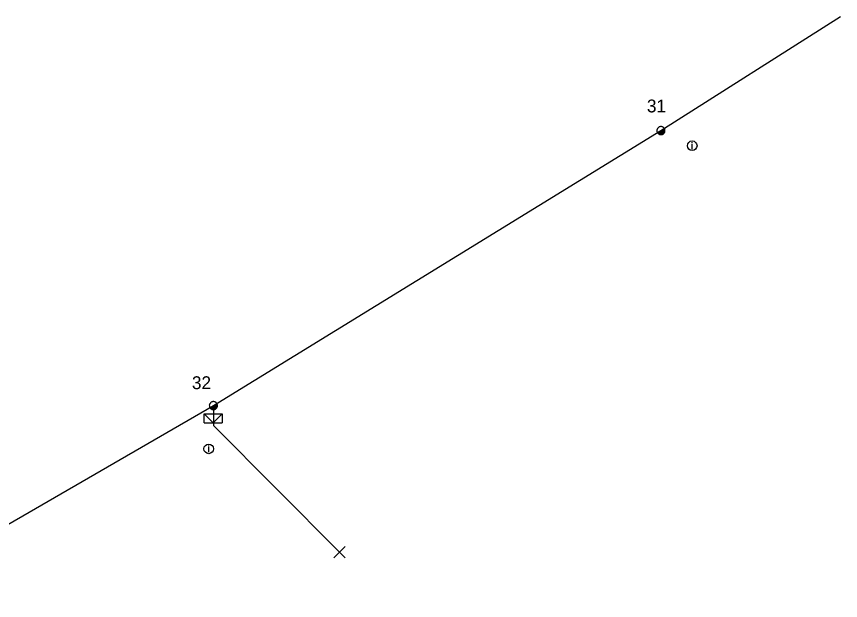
# Model space of a CAD drawing. Extents: x -536148 to -535465, y -1201639 to -1201298.
# Drawn here: x -535529.3 to -535465.3, y -1201539 to -1201493.6 of the extents above; entities that cross this region are included whole.
import ezdxf

# ---------------------------------------------------------------- set-up
doc = ezdxf.new("R2010")
doc.units = 0
for name, color, linetype in [('CHRAN_NN', 7, 'Continuous'), ('CIZÍ_PODZEM', 7, 'Continuous'), ('CIZÍ_PODZEM_POPIS', 7, 'Continuous'), ('DOPLŇ_POPISY', 7, 'Continuous'), ('ELE_EON', 7, 'Continuous'), ('ELE_EON_POPIS', 7, 'Continuous'), ('KN_VKP_HRAN_NEZNATELNÁ', 7, 'Continuous'), ('KN_VKP_HRAN_SPORNÁ', 7, 'Continuous'), ('PK_HRAN_POHYBLIVÁ', 7, 'Continuous'), ('PLG_EXPORT_GPE', 7, 'Continuous')]:
    doc.layers.add(name, color=color, linetype=linetype)

# ---------------------------------------------------------------- blocks, each defined once
blk = doc.blocks.new('NN440')
at = {"layer": 'ELE_EON_POPIS'}
for points in [[(0.63, 0), (0.63, 0.06), (0.62, 0.13), (0.6, 0.19), (0.58, 0.25), (0.55, 0.31), (0.51, 0.37), (0.47, 0.42), (0.42, 0.46), (0.37, 0.51), (0.32, 0.54), (0.26, 0.57), (0.2, 0.59), (0.13, 0.61), (0.07, 0.62), (0, 0.63), (-0.06, 0.62), (-0.13, 0.61), (-0.19, 0.59), (-0.26, 0.57), (-0.31, 0.54), (-0.37, 0.51), (-0.42, 0.46), (-0.47, 0.42), (-0.51, 0.37), (-0.54, 0.31), (-0.57, 0.25), (-0.6, 0.19), (-0.62, 0.13), (-0.63, 0.06), (-0.63, 0), (-0.63, -0.07), (-0.62, -0.14), (-0.6, -0.2), (-0.57, -0.26), (-0.54, -0.32), (-0.51, -0.37), (-0.47, -0.43), (-0.42, -0.47), (-0.37, -0.51), (-0.31, -0.55), (-0.26, -0.58), (-0.19, -0.6), (-0.13, -0.62), (-0.06, -0.63), (0, -0.63), (0.07, -0.63), (0.13, -0.62), (0.2, -0.6), (0.26, -0.58), (0.32, -0.55), (0.37, -0.51), (0.42, -0.47), (0.47, -0.43), (0.51, -0.37), (0.55, -0.32), (0.58, -0.26), (0.6, -0.2), (0.62, -0.14), (0.63, -0.07), (0.63, 0)], [(-0.63, 0), (0.63, 0)], [(-0.6, -0.18), (0.57, -0.18)], [(-0.51, -0.32), (0.5, -0.32)], [(-0.37, -0.47), (0.35, -0.47)]]:
    blk.add_lwpolyline(points, dxfattribs=at)
blk = doc.blocks.new('NN770')
at = {"layer": 'CIZÍ_PODZEM_POPIS'}
for p, q in [((0.002, 0.187), (0.002, 0.263)), ((0.002, -0.276), (0.002, 0.111))]:
    blk.add_line(p, q, dxfattribs=at)
blk.add_circle((0, -0.008), 0.375, dxfattribs=at)
blk = doc.blocks.new('NN800')
at = {"layer": 'ELE_EON'}
for points in [[(-0.442, 0.442), (0.442, -0.442)], [(-0.442, -0.442), (0.442, 0.442)]]:
    blk.add_lwpolyline(points, dxfattribs=at)
blk = doc.blocks.new('NN630')
at = {"layer": 'CIZÍ_PODZEM'}
for points in [[(-0.003, -0.7), (-0.703, 0)], [(-0.703, -0.7), (-0.703, 0), (0.697, 0), (0.697, -0.7)], [(-0.003, -0.7), (0.697, 0)], [(-0.703, -0.7), (0.697, -0.7)]]:
    blk.add_lwpolyline(points, dxfattribs=at)

msp = doc.modelspace()

# ---------------------------------------------------------------- linework, layer by layer
at = {"layer": 'CHRAN_NN'}
msp.add_lwpolyline([(-535514.019, -1201523.838), (-535514.019, -1201524.473), (-535514.019, -1201525.386), (-535504.209, -1201535.215)], dxfattribs=at)
at = {"layer": 'ELE_EON'}
msp.add_lwpolyline([(-535540.23, -1201538.98), (-535514.019, -1201523.838), (-535479.236, -1201502.472), (-535465.278, -1201493.607)], dxfattribs=at)

# ---------------------------------------------------------------- block references
at = {"layer": 'DOPLŇ_POPISY', "xscale": 0.5}
for p, yscale, rotation in [((-535479.237, -1201502.473), 0.5000000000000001, 32.42073334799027), ((-535514.018, -1201523.839), 0.5, 31.56097502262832)]:
    msp.add_blockref('NN440', p, dxfattribs=dict(at, yscale=yscale, rotation=rotation))
at = {"layer": 'KN_VKP_HRAN_NEZNATELNÁ'}
msp.add_blockref('NN800', (-535504.209, -1201535.215), dxfattribs=at)
at = {"layer": 'KN_VKP_HRAN_SPORNÁ'}
msp.add_blockref('NN630', (-535514.019, -1201524.473), dxfattribs=at)
at = {"layer": 'PK_HRAN_POHYBLIVÁ'}
for p in [(-535476.806, -1201503.643), (-535514.375, -1201527.19)]:
    msp.add_blockref('NN770', p, dxfattribs=at)

# ---------------------------------------------------------------- texts
at = {"layer": 'PLG_EXPORT_GPE'}
for s, p in [('31', (-535480.325, -1201501.059)), ('32', (-535515.686, -1201522.559))]:
    msp.add_text(s, height=1, dxfattribs=at).set_placement(p)

doc.saveas('drawing.dxf')
